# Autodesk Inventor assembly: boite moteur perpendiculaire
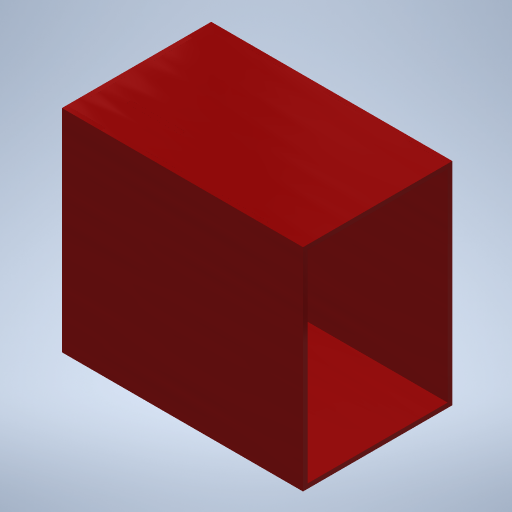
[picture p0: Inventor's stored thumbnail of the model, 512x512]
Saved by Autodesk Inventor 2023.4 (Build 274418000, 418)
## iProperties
Part Number: boite moteur perpendiculaire
Material: Générique
Document SubType Name: Assembly
Designer: ficho
Author: ficho
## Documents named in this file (9)
- D:\travail\année 2019-2020\réforme\avant février\IT\boite moteur perpendiculaire.iam
- D:\travail\année 2019-2020\réforme\avant février\IT\dessous boite bielle manivelle.ipt
- D:\travail\année 2019-2020\réforme\avant février\IT\support moteur boite bielle manivelle.ipt
- D:\travail\année 2019-2020\réforme\avant février\IT\corps moto reducteur.ipt
- D:\travail\année 2019-2020\réforme\avant février\IT\flanc avant boite bielle manivelle.ipt
- D:\travail\année 2019-2020\réforme\avant février\IT\arduino uno et shield.iam
- D:\travail\année 2019-2020\réforme\avant février\IT\flanc arrière boite bielle manivelle.ipt
- D:\travail\année 2019-2020\réforme\avant février\IT\dessus boite bielle manivelle.ipt
- D:\travail\année 2019-2020\réforme\avant février\IT\Fond boite bielle manivelle.ipt
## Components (8 placed, 8 different names)
1. dessous boite bielle manivelle:1 — Placage:1, Placage:2, Placage:3, Affleurement:1, Affleurement:2, Affleurement:4, Placage:7
2. support moteur boite bielle manivelle:1 — Placage:1, Placage:2, Placage:3, Logement:1, Placage:4, Placage:5
3. corps moto reducteur:1 — Logement:1, Placage:4
4. flanc avant boite bielle manivelle:1 — Affleurement:1, Affleurement:3
5. arduino uno et shield:1 [sub-assembly] — Placage:5, Placage:6, Placage:7
6. flanc arrière boite bielle manivelle:1 — Affleurement:2
7. dessus boite bielle manivelle:1 — Affleurement:3
8. Fond boite bielle manivelle:1 — Affleurement:4, Placage:6
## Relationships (12: Mate 7, Flush 4, Insert 1)
- Placage:1 [Mate]: dessous boite bielle manivelle:1 ↔ support moteur boite bielle manivelle:1
- Placage:2 [Mate]: dessous boite bielle manivelle:1 ↔ support moteur boite bielle manivelle:1
- Placage:3 [Mate]: dessous boite bielle manivelle:1 ↔ support moteur boite bielle manivelle:1
- Logement:1 [Insert]: support moteur boite bielle manivelle:1 ↔ corps moto reducteur:1
- Placage:4 [Mate]: support moteur boite bielle manivelle:1 ↔ corps moto reducteur:1
- Affleurement:1 [Flush]: dessous boite bielle manivelle:1 ↔ flanc avant boite bielle manivelle:1
- Affleurement:2 [Flush]: dessous boite bielle manivelle:1 ↔ flanc arrière boite bielle manivelle:1
- Affleurement:3 [Flush]: flanc avant boite bielle manivelle:1 ↔ dessus boite bielle manivelle:1
- Affleurement:4 [Flush]: dessous boite bielle manivelle:1 ↔ Fond boite bielle manivelle:1
- Placage:5 [Mate]: support moteur boite bielle manivelle:1 ↔ arduino uno et shield:1
- Placage:6 [Mate]: arduino uno et shield:1 ↔ Fond boite bielle manivelle:1
- Placage:7 [Mate]: dessous boite bielle manivelle:1 ↔ arduino uno et shield:1
